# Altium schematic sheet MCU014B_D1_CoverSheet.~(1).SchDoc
size 558 x 431 mm; Date: Not shown in title block; ApprovedBy: Not shown in title block; CheckedBy: Not shown in title block; Author: Not shown in title block; CompanyName: Not shown in title block; DrawnBy: Vince Rodriguez; Engineer: Vince Rodriguez; Organization: Not shown in title block; Address1: Not shown in title block; Address2: Not shown in title block; Address3: Not shown in title block; Address4: Not shown in title block; DocumentNumber: 1; Revision: Use project parameter SCH_Rev; SheetNumber: 1; SheetTotal: 7; PageSetup: Record=PageOptions¦CenterHorizontal=True¦CenterVertical=True¦PrintScale=1.00¦XCorrection=1.00¦YCorrection=1.00¦PrintKind=0¦BorderSize=5000000¦LeftOffset=0¦BottomOffset=0¦Orientation=2¦PaperLength=1000¦PaperWidth=1000¦Scale=100¦PaperSource=15¦PrintQuality=600¦MediaType=1¦DitherType=10¦PaperKind=Letter¦PrintScaleMode=1
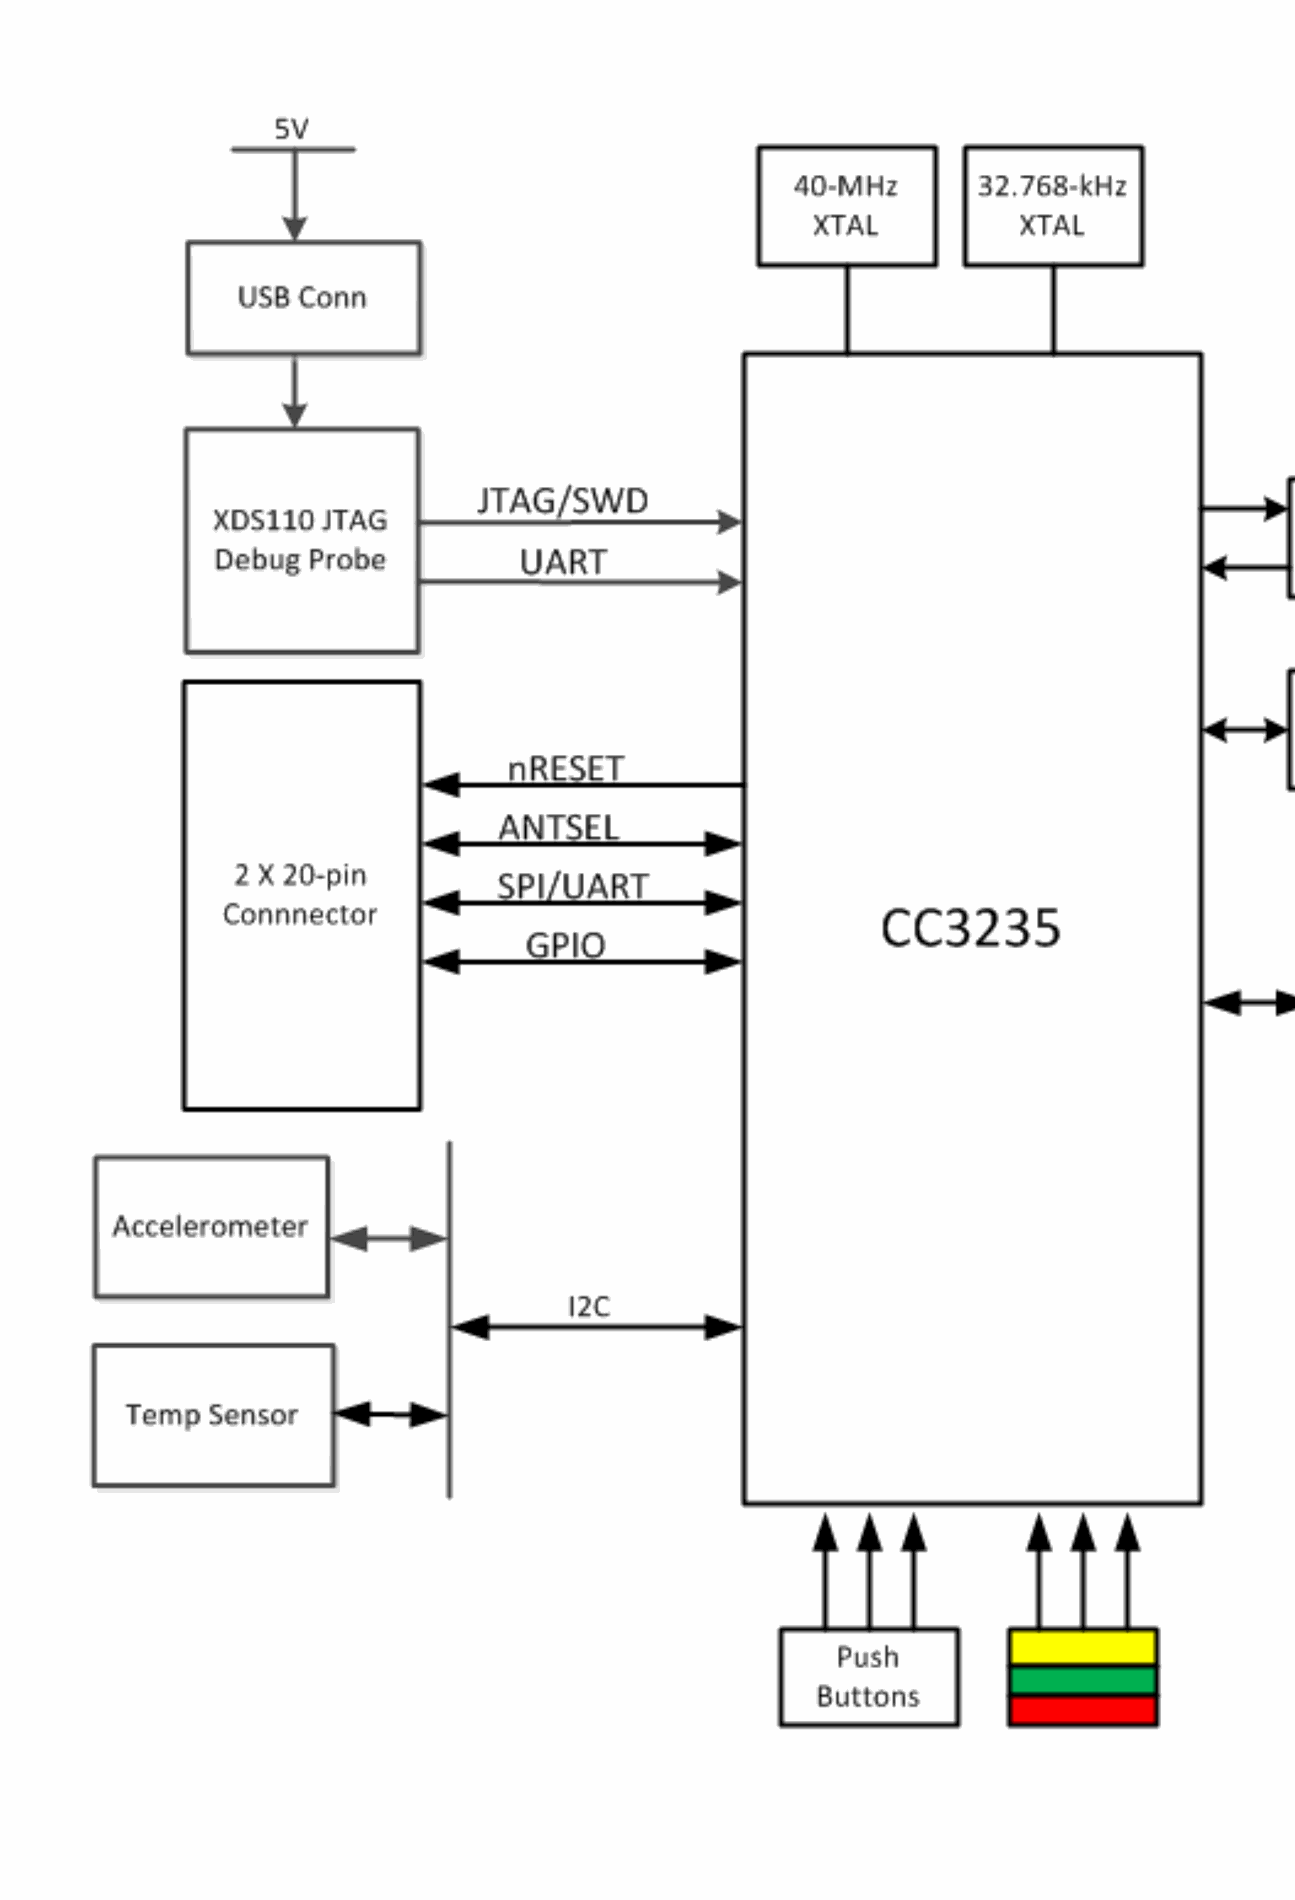
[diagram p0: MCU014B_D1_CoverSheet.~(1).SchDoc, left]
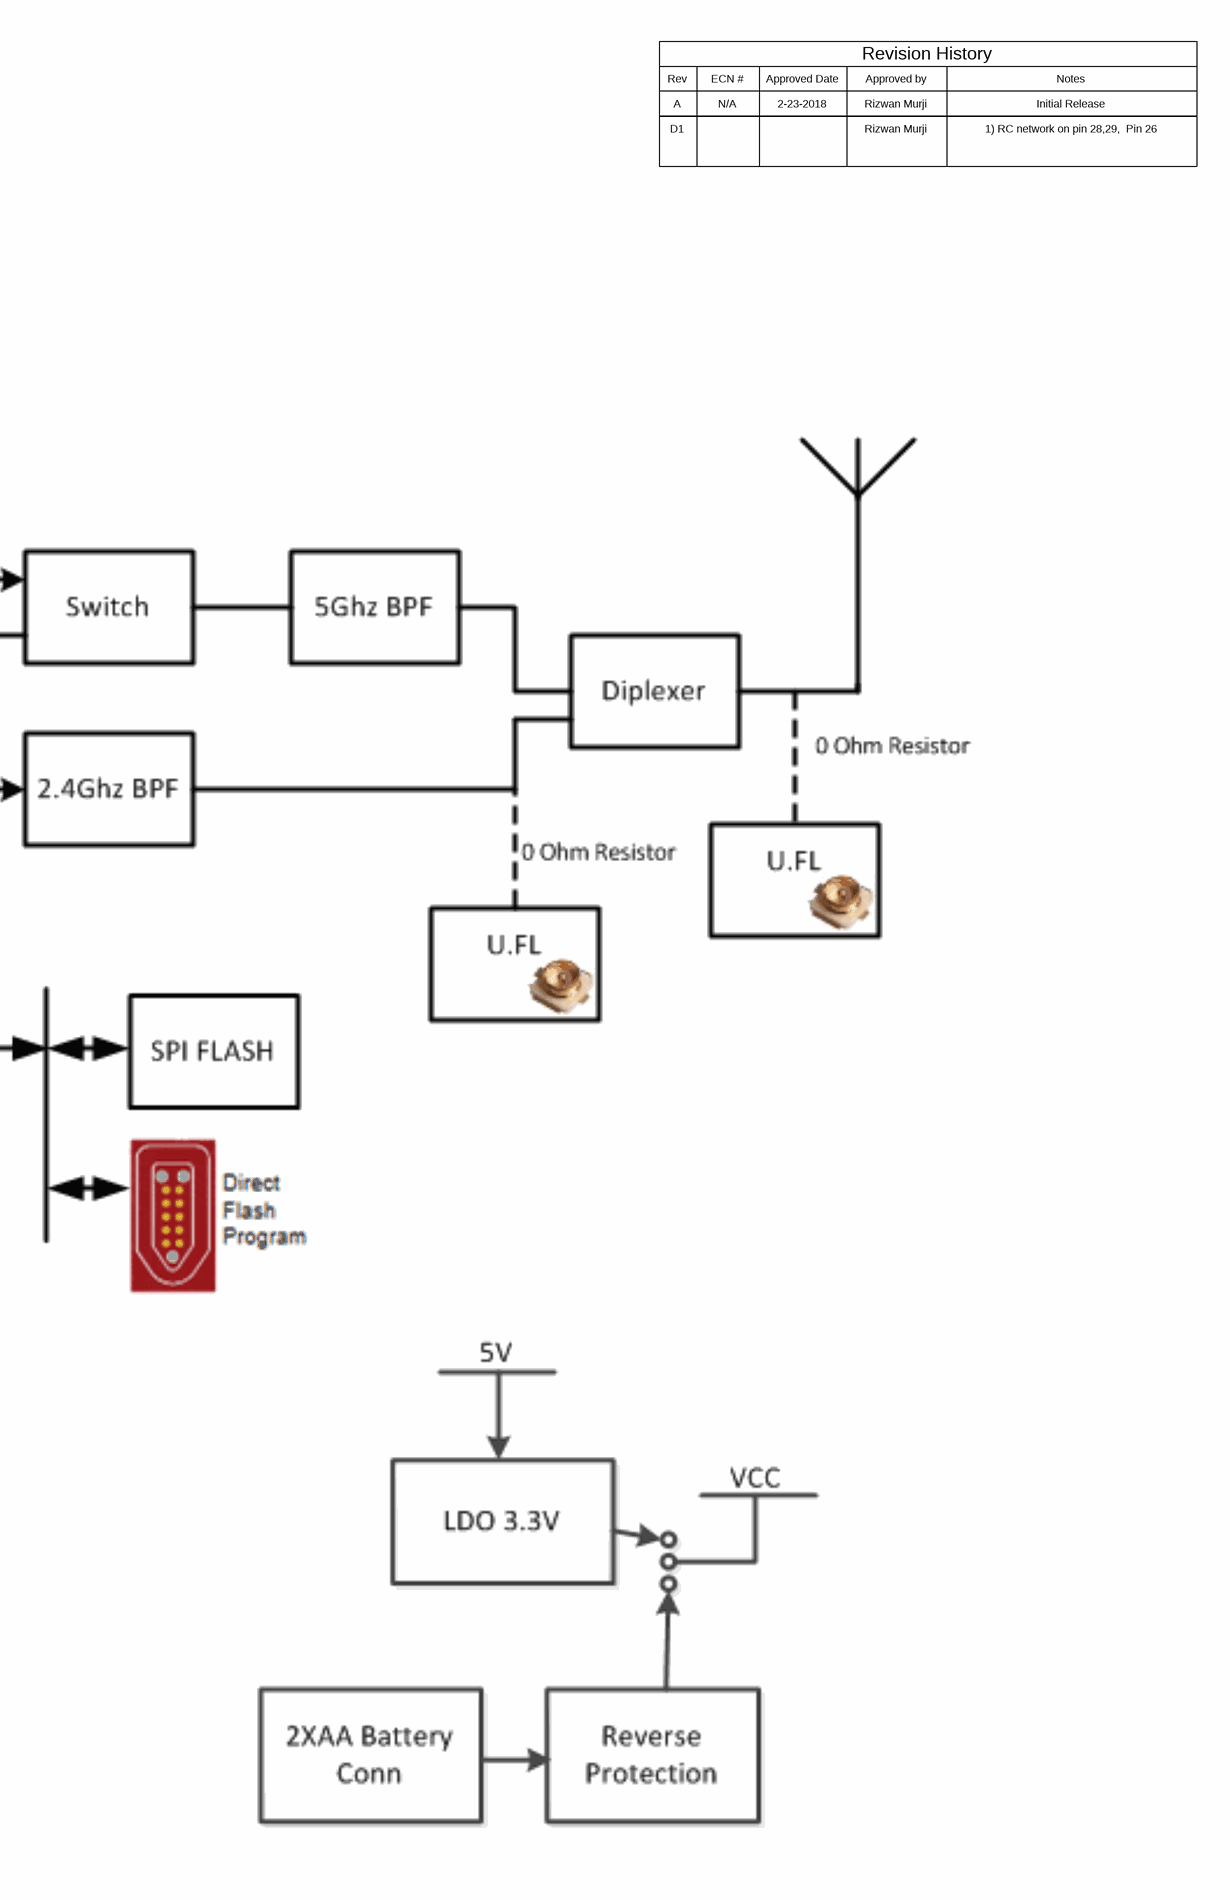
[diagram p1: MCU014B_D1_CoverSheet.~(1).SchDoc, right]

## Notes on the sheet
- Rev
- ECN #
- Approved Date
- Approved by
- Revision History
- Notes
- A
- D1
- N/A
- 2-23-2018
- Rizwan Murji
- Initial Release
- 1) RC network on pin 28,29,  Pin 26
